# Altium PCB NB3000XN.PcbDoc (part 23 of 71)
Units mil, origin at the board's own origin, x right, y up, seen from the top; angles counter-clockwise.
Board outline 9527.56 x 6929.77 mil, 6 copper layers (Top Layer, GND+SHIELD, MidLayer1, MidLayer2, P2 - 3V3+5V0, Bottom Layer), stack 62.375 mil thick; 832 components, 1027 nets, 4655 pads, 4981 vias.
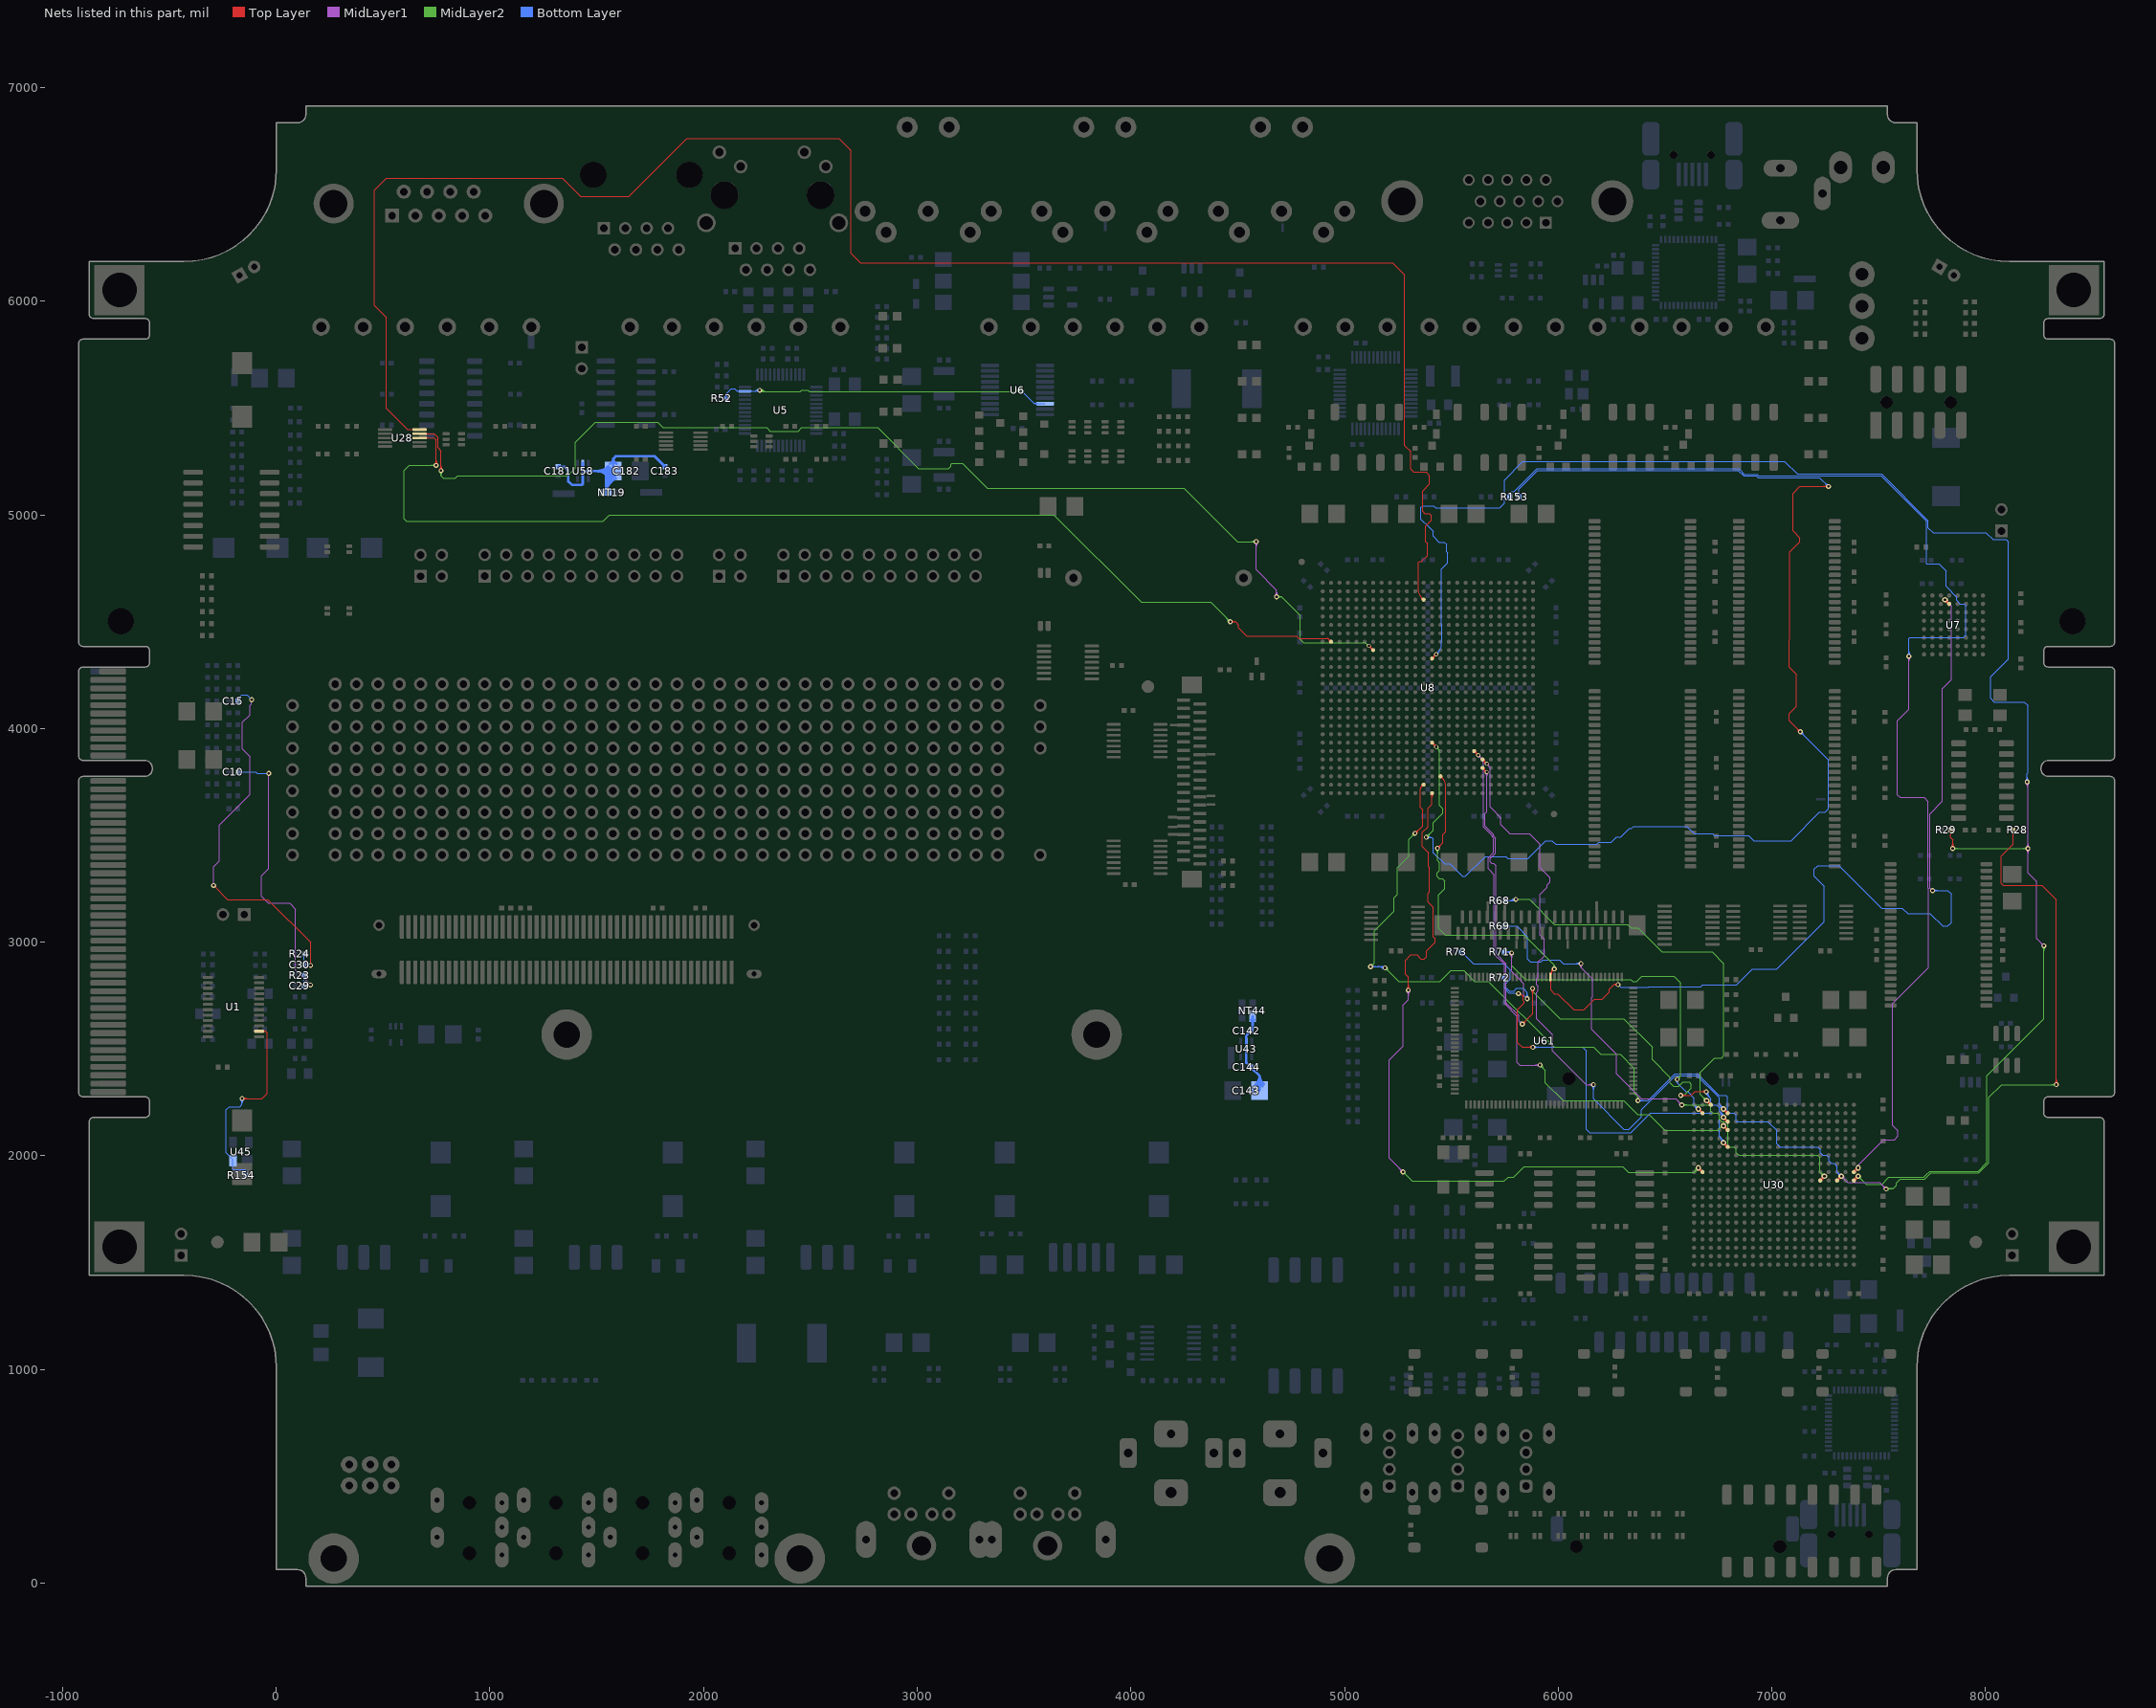
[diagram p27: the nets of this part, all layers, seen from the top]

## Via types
v1: diameter 23, hole 11.81, Top Layer to Bottom Layer, 3672 vias
v2: diameter 26, hole 11.81, Top Layer to Bottom Layer, 461 vias
v3: diameter 19, hole 11.81, Top Layer to Bottom Layer, tented both sides, 396 vias
v4: diameter 23.62, hole 11.81, Top Layer to Bottom Layer, 288 vias
v5: diameter 20, hole 11.81, Top Layer to Bottom Layer, 91 vias
v6: diameter 23, hole 11.81, Top Layer to Bottom Layer, tented both sides, 50 vias
v7: diameter 31, hole 11.81, Top Layer to Bottom Layer, 15 vias
v8: diameter 27.56, hole 11.81, Top Layer to Bottom Layer, tented both sides, 4 vias
v9: diameter 29, hole 11.81, Top Layer to Bottom Layer, 3 vias
v10: diameter 21, hole 11.81, Top Layer to Bottom Layer, 1 vias

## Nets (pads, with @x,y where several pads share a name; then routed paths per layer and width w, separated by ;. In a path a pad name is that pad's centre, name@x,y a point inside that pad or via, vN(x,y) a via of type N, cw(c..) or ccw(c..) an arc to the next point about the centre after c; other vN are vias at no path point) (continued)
CODEC_AUD.L: C10.2 C29.1 R23.1 | length 1510.1
  MidLayer1 w4: v1(-35,3790) -35.7,3790 -35.81,3789.89 -35.81,3344.19 -69.25,3310.75 -69.25,3214.25 -37.69,3182.69 62.31,3182.69 90.19,3154.81 90.19,2870.71 v1(160.86,2800.04)
  Bottom Layer w4: C10.2@-179.33,3795.91 -95,3795.91 -89.09,3790 v1(-35,3790) ; C29.1@130.67,2795 C29.1@131.18,2795.51 ; R23.1@130.67,2844.49 R23.1@131.18,2845 C29.1@131.18,2795.51 ; C29.1@132.1,2793.89 cw(c144.6,2784.27) 144.6,2800.04 ; C29.1@135.27,2791.45 cw(c152.73,2778.01) v1@152.73,2800.04 ; C29.1@137.61,2801.94 ccw(c142.19,2806.52) C29.1@142.19,2800.04 ; C29.1@138.44,2789.01 cw(c160.86,2771.75) v1(160.86,2800.04) 135.71,2800.04 C29.1@131.18,2795.51 ; v1@154.14,2793.32 ccw(c137.92,2777.11) 137.92,2800.04 ccw(c137.92,2822.98) v1@154.14,2806.76 ; v1@156.97,2796.15 ccw(c147.58,2786.76) 147.58,2800.04 ccw(c147.58,2813.32) v1@156.97,2803.93
CODEC_AUD.R: C15.2 C30.1 R24.1 | length 1882
  Top Layer w4: v1(-293.14,3265.71) -227.44,3200 -40,3200 160.86,2999.14 v1(160.86,2891.71)
  MidLayer1 w4: v1(-293.14,3265.71) -293.14,3353.62 -266.31,3380.45 -266.31,3548.69 -122.48,3692.52 -122.48,3869.56 -138.29,3885.37 ; -138.66,3885.37 -157.48,3904.19 -157.48,4029.34 -123,4063.82 -123,4107.81 -116.52,4114.29 v1@-116.52,4135
  Bottom Layer w4: C15.2@-179.33,4128.64 -179.33,4138.55 -160.94,4156.94 -136.94,4156.94 v1(-115,4135) ; R24.1@130.67,2944.49 R24.1@131.18,2945 131.18,2895.51 C30.1@130.67,2895 ; C30.1@140.11,2895 cw(c140.11,2871.62) v1@156.91,2887.88 ; 145.87,2895 ccw(c145.87,2906.69) v1@154.14,2898.43 ; 149.55,2895 cw(c149.55,2880.76) v1@159.78,2890.66 ; v1@154.03,2885.1 ccw(c130.67,2862.49) C30.1@130.67,2895 ; v1(160.86,2891.71) 157.56,2895 C30.1@130.67,2895
CODEC_RST: R154.1 U1.14 U45.2 | length 1071.8
  Top Layer w4: v1(-159.81,2268.37) -66.63,2268.37 -43.14,2291.86 -43.14,2575.03 -51.14,2583.03 U1.14@-79.84,2583.03 ; v1@-155.92,2264.49 cw(c-146.53,2255.1) -146.53,2268.37 cw(c-146.53,2281.65) v1@-155.92,2272.26 ; v1@-153.09,2261.66 cw(c-136.87,2245.44) -136.87,2268.37 cw(c-136.87,2291.31) v1@-153.09,2275.09 ; U1.14@-60.1,2579.43 cw(c-51.42,2570.75) -51.42,2583.03 cw(c-51.42,2595.31) U1.14@-60.1,2586.63
  Bottom Layer w4: v1@-166.53,2261.66 cw(c-182.74,2245.44) -159.81,2245.44 cw(c-136.87,2245.44) v1@-153.09,2261.66 ; v1@-163.7,2264.49 cw(c-173.09,2255.1) -159.81,2255.1 cw(c-146.53,2255.1) v1@-155.92,2264.49 ; v1(-159.81,2268.37) -159.81,2240 -169.81,2230 -220,2230 -235,2215 -235,2015 -202.85,1982.85 U45.2@-202.85,1976.69 -202.85,1937.85 -200,1935 -146.32,1935 -141.32,1930 R154.1@-141.32,1910
COMA: C142.1 C143.2 C144.1 NT44.2 U43.2 | length 667.1
  Bottom Layer w12: C144.1@4555.84,2415 ccw(c4541.81,2415) 4551.73,2424.92 ccw(c4561.65,2434.84) C144.1@4561.65,2420.81 ; C142.1@4555.84,2585 cw(c4541.81,2585) 4551.73,2575.08 cw(c4561.65,2565.16) C142.1@4561.65,2579.19 ; C142.1@4557.54,2589.11 ccw(c4528.04,2618.61) 4569.76,2618.61 ; C144.1@4561.65,2409.19 cw(c4561.65,2395.16) 4571.57,2405.08 cw(c4581.49,2415) C144.1@4567.46,2415 ; NT44.2@4562.87,2636.75 cw(c4546.23,2620.11) 4569.76,2620.11 cw(c4593.3,2620.11) NT44.2@4576.66,2636.75 ; NT44.2@4569.76,2653.9 4569.76,2593.11 C142.1@4561.65,2585 4540,2563.35 U43.2@4540,2537.4 4540,2436.65 C144.1@4561.65,2415 4602.99,2373.66 ; C143.2@4583.64,2336.12 ccw(c4556.91,2373.66) 4602.99,2373.66 ; C143.2@4590.6,2326.35 ccw(c4573.48,2350.38) 4602.99,2350.38 ccw(c4632.5,2350.38) C143.2@4615.39,2326.35 ; C143.2@4602.99,2305 4602.99,2373.66 ; C143.2@4622.35,2336.12 cw(c4649.07,2373.66) 4602.99,2373.66
COMB: C181.1 C182.2 C183.1 NT19.2 U58.2 | length 1566.9
  Bottom Layer w12: C181.1@1320,5225.67 1349.33,5225.67 1366.58,5208.42 1366.58,5158.42 1385,5140 1430,5140 1435,5145 1435,5205 ; C181.1@1324.11,5221.56 cw(c1334.03,5211.64) 1334.03,5225.67 cw(c1334.03,5239.7) C181.1@1324.11,5229.78 ; U58.2@1435,5242.4 1435,5205 ; NT19.2@1537,5112.13 ccw(c1520.36,5128.77) 1543.9,5128.77 ccw(c1567.43,5128.77) NT19.2@1550.79,5112.13 ; NT19.2@1543.9,5099.52 cw(c1620.99,5099.52) C182.2@1590.64,5170.39 ; NT19.2@1543.9,5105.24 1543.9,5171.4 C182.2@1577.5,5205 ; NT19.2@1543.9,5117.71 cw(c1613.2,5117.71) C182.2@1585.91,5181.42 ; 1543.9,5135.91 cw(c1605.41,5135.91) C182.2@1581.19,5192.45 ; 1543.9,5154.1 cw(c1597.61,5154.1) C182.2@1576.46,5203.48 ; C182.2@1543.9,5172.3 cw(c1589.82,5172.3) C182.2@1571.74,5214.51 ; C182.2@1553.9,5181.4 ccw(c1496.94,5124.44) 1496.94,5205 ccw(c1496.94,5285.56) C182.2@1553.9,5228.6 ; C182.2@1562.39,5189.89 ccw(c1525.91,5153.41) 1525.91,5205 ccw(c1525.91,5256.59) C182.2@1562.39,5220.11 ; C182.2@1562.79,5238.89 ccw(c1551.2,5262.5) 1577.5,5262.5 ccw(c1603.8,5262.5) C182.2@1592.21,5238.89 ; C183.1@1814.19,5225.67 ccw(c1800.16,5225.67) 1810.08,5235.59 ccw(c1820,5245.51) C183.1@1820,5231.48 ; C183.1@1820,5225.67 1770.67,5275 1590,5275 1577.5,5262.5 C182.2@1577.5,5205 1435,5205
CRS_U: R52.1 U5.23 U6.8 | length 1968.1
  MidLayer2 w4: v1(2262.86,5583.71) 2269.06,5577.5 2452.25,5577.5 2459.27,5584.52 2488.69,5584.52 2495.71,5577.5 3478.65,5577.5 v1(3484.86,5583.71) ; v1@2263.92,5584.77 ccw(c2281.47,5602.32) 2281.47,5577.5 ; v1@2266.75,5587.6 ccw(c2291.12,5611.97) 2291.12,5577.5 ; v1@2269.57,5590.43 ccw(c2300.78,5621.63) 2300.78,5577.5 ; 3446.94,5577.5 ccw(c3446.94,5621.63) v1@3478.14,5590.43 ; 3456.59,5577.5 ccw(c3456.59,5611.97) v1@3480.97,5587.6 ; 3466.25,5577.5 ccw(c3466.25,5602.32) v1@3483.8,5584.77
  Bottom Layer w4: R52.1@2100.04,5552.5 ccw(c2088.21,5566.03) 2106.18,5566.03 ; R52.1@2102.68,5549.49 ccw(c2095.92,5557.22) 2106.18,5557.22 ccw(c2116.44,5557.21) R52.1@2109.68,5549.49 ; R52.1@2106.18,5545 2106.18,5566.03 ; R52.1@2112.32,5552.5 cw(c2124.16,5566.03) 2106.18,5566.03 ; U5.23@2167.19,5575.75 ccw(c2160.36,5568.93) 2160.36,5578.58 ccw(c2160.36,5588.24) U5.23@2167.19,5581.41 ; U5.23@2219.9,5575.75 cw(c2226.73,5568.93) 2226.73,5578.58 cw(c2226.73,5588.24) U5.23@2219.9,5581.41 ; 2227.55,5578.58 ccw(c2227.55,5619.02) v1@2256.14,5590.43 ; 2237.21,5578.58 ccw(c2237.21,5609.36) v1@2258.97,5587.6 ; 2246.86,5578.58 ccw(c2246.86,5599.7) v1@2261.8,5584.77 ; 2252.29,5578.58 cw(c2252.29,5573.15) v1@2256.14,5576.99 ; v1(2262.86,5583.71) 2257.73,5578.58 U5.23@2193.54,5578.58 2156.86,5578.58 2145.4,5590.04 2130.19,5590.04 2106.18,5566.03 ; v1@3484.86,5574.21 cw(c3484.86,5551.27) 3501.07,5567.49 cw(c3517.29,5583.71) v1@3494.36,5583.71 ; v1@3484.86,5578.21 cw(c3484.86,5564.93) 3494.25,5574.32 cw(c3503.64,5583.71) v1@3490.36,5583.71 ; v1(3484.86,5583.71) 3547.54,5521.02 U6.8@3598.94,5521.02 ; U6.8@3560.62,5516.17 ccw(c3548.91,5504.47) 3548.91,5521.02 ccw(c3548.92,5537.58) U6.8@3560.62,5525.87
DAC.CLK: U8.C13 U28.10 | length 8540.9
  Top Layer w4: U28.10@640.42,5396.54 ccw(c633.59,5389.71) 633.59,5399.37 ccw(c633.59,5409.03) U28.10@640.42,5402.2 ; U28.10@670.71,5399.37 615,5399.37 515,5499.37 515,5925 460,5980 460,6520 515,6575 1340,6575 1425,6490 1650,6490 1922,6762 2633,6762 2690,6705 2690,6225 2735,6180 5225,6180 5281.86,6123.14 5281.86,5325.04 5309.86,5297.04 5309.86,5294 ; 5309.86,5250.04 5309.86,5294 ; U8.C13@5362.97,4603.39 ccw(c5345.25,4603.39) 5357.78,4615.92 ; U8.C13@5370.31,4610.73 cw(c5370.31,4628.45) 5357.78,4615.92 ; 5309.86,5294 5309.86,5214.14 5323.96,5200.04 5381.86,5200.04 5398.52,5183.37 5398.52,5145.71 5365.19,5112.37 5365.19,5016.71 5375.52,5006.37 5398.52,5006.37 5406.86,4998.04 5406.86,4975.04 5379.19,4947.37 5379.19,4875.04 5387.5,4866.73 5387.5,4810.06 5360.44,4783 5350,4783 5346.45,4779.45 5346.45,4773 5346.45,4724.74 5346.45,4720 5346.45,4710 5346.45,4643.27 ccw(c5385.13,4643.27) 5357.78,4615.92
DAC.CS: U8.J7 U28.9 | length 5946.3
  Top Layer w4: U28.9@670.71,5379.69 740.31,5379.69 756.86,5363.14 756.86,5314.71 771.52,5300.04 v1(771.52,5207.37) ; U28.9@701,5376.86 cw(c707.83,5370.03) 707.83,5379.69 cw(c707.83,5389.34) U28.9@701,5382.51 ; v1@764.81,5214.09 ccw(c748.59,5230.31) 771.52,5230.31 ccw(c794.46,5230.31) v1@778.24,5214.09 ; v1@767.64,5211.26 ccw(c758.25,5220.65) 771.52,5220.65 ccw(c784.8,5220.65) v1@775.41,5211.26 ; v3(5114.41,4386.85) U8.J7@5134.09,4367.17 ; U8.J7@5126.59,4367.17 ccw(c5108.49,4367.17) 5121.29,4379.97 ccw(c5134.09,4392.77) U8.J7@5134.09,4374.67 ; U8.J7@5126.75,4367.17 ccw(c5109.03,4367.17) 5121.56,4379.7 ccw(c5134.09,4392.23) U8.J7@5134.09,4374.51 ; 5127.21,4374.05 ccw(c5114.41,4361.24) 5114.41,4379.35 cw(c5114.41,4361.24) 5127.21,4374.05 ; 5127.21,4374.05 cw(c5140.02,4386.85) 5121.91,4386.85 ccw(c5140.02,4386.85) 5127.21,4374.05
  MidLayer1 w4: v1@4580.14,4868.32 cw(c4563.92,4852.11) 4586.86,4852.11 cw(c4609.79,4852.11) v1@4593.57,4868.32 ; v1@4582.97,4871.15 cw(c4573.58,4861.76) 4586.86,4861.76 cw(c4600.14,4861.76) v1@4590.75,4871.15 ; v1(4586.86,4875.04) 4586.86,4743.39 4681.86,4648.39 v1(4681.86,4616.71) ; v1@4675.14,4623.43 ccw(c4658.92,4639.64) 4681.86,4639.64 ccw(c4704.79,4639.64) v1@4688.57,4623.43 ; v1@4677.97,4620.6 ccw(c4668.58,4629.99) 4681.86,4629.99 ccw(c4695.14,4629.99) v1@4685.75,4620.6
  MidLayer2 w4: v1@764.81,5200.66 cw(c748.59,5184.44) 771.52,5184.44 cw(c794.46,5184.44) v1@778.24,5200.66 ; v1@767.64,5203.49 cw(c758.25,5194.1) 771.52,5194.1 cw(c784.8,5194.1) v1@775.41,5203.49 ; v1(771.52,5207.37) 771.52,5183.48 782.72,5172.28 837.28,5172.28 848.71,5183.71 1365.02,5183.71 1400,5218.69 1400,5340.2 1493.5,5433.71 1786.29,5433.71 1810,5410 2294.81,5410 2312.62,5392.19 2443.04,5392.19 2459.39,5408.54 2815.03,5408.54 3006.38,5217.19 3147.38,5217.19 3157.81,5227.62 3157.81,5235.84 3163.68,5241.71 3211.98,5241.71 3328.65,5125.04 4248.52,5125.04 4498.52,4875.04 v1(4586.86,4875.04) ; v1@4580.14,4868.32 ccw(c4563.92,4852.11) 4563.92,4875.04 ccw(c4563.92,4897.98) v1@4580.14,4881.76 ; v1@4582.97,4871.15 ccw(c4573.58,4861.76) 4573.58,4875.04 ccw(c4573.58,4888.32) v1@4582.97,4878.93 ; v1(4681.86,4616.71) 4705.19,4616.71 4770.79,4551.11 4792,4529.9 4792,4418 4807.64,4402.36 4860,4402.36 4870,4402.36 4997.36,4402.36 5090.9,4402.36 cw(c5090.9,4388.31) 5100.83,4398.24 ; v1@4685.75,4612.82 cw(c4695.14,4603.43) 4695.14,4616.71 cw(c4695.14,4629.99) v1@4685.75,4620.6 ; v1@4688.57,4609.99 cw(c4704.79,4593.77) 4704.79,4616.71 cw(c4704.79,4639.64) v1@4688.57,4623.43 ; v3@5106.94,4386.2 ccw(c5088.9,4384.62) 5100.54,4398.49 ccw(c5112.18,4412.36) v3@5113.76,4394.32
DAC.DIN: U8.H2 U28.8 | length 5482.2
  Top Layer w4: U28.8@698.18,5360 U28.8@676.2,5360 ; U28.8@701,5357.17 cw(c707.83,5350.34) 707.83,5360 cw(c707.83,5369.66) U28.8@701,5362.83 ; v1@741.81,5238.76 ccw(c725.59,5254.98) 748.52,5254.98 ccw(c771.46,5254.98) v1@755.24,5238.76 ; v1@744.64,5235.93 ccw(c735.25,5245.32) 748.52,5245.32 ccw(c761.8,5245.32) v1@752.41,5235.93 ; v1(748.52,5232.04) 748.52,5351.48 740,5360 U28.8@676.2,5360 ; v1(4465.19,4500.04) 4489.96,4500.04 4505,4485 4505,4471.31 4542.44,4433.87 4759,4433.87 4774.01,4433.87 4785.84,4422.04 4790.84,4422.04 4801,4422.04 4860,4422.04 4870,4422.04 4917.53,4422.04 cw(c4917.53,4411.89) 4924.71,4419.07 ; v1@4469.08,4496.15 cw(c4478.47,4486.76) 4478.47,4500.04 cw(c4478.47,4513.32) v1@4469.08,4503.93 ; v1@4471.91,4493.32 cw(c4488.13,4477.11) 4488.13,4500.04 cw(c4488.13,4522.98) v1@4471.91,4506.76 ; U8.H2@4929.9,4406.54 ccw(c4912.17,4406.54) 4924.71,4419.07 ; U8.H2@4937.24,4413.88 cw(c4937.24,4431.6) 4924.71,4419.07 ; U28.8@676.2,5360 U28.8@670.71,5360 U28.8@676.2,5360
  MidLayer2 w4: v1@741.81,5225.32 ccw(c725.59,5209.11) 725.59,5232.04 ccw(c725.59,5254.98) v1@741.81,5238.76 ; v1@744.64,5228.15 ccw(c735.25,5218.76) 735.25,5232.04 ccw(c735.25,5245.32) v1@744.64,5235.93 ; v1(748.52,5232.04) 622.04,5232.04 598.52,5208.52 598.52,4981.48 610,4970 1530,4970 1560.04,5000.04 1635,5000.04 3625,5000 ; 3620,5000 3625,5000 ; v1@4455.69,4500.04 ccw(c4432.76,4500.04) 4448.97,4516.26 ccw(c4465.19,4532.48) v1@4465.19,4509.54 ; v1@4459.69,4500.04 ccw(c4446.41,4500.04) 4455.8,4509.43 ccw(c4465.19,4518.82) v1@4465.19,4505.54 ; v1(4465.19,4500.04) 4373.52,4591.71 4048.52,4591.71 3640.23,5000 3625,5000
DB_CLK1: R153.1 U30.A9 | length 6069
  Top Layer w8: U30.A9@7384.02,1924.06 v2(7403.7,1943.74) ; U30.A9@7384.02,1929.9 ccw(c7384.02,1944) 7393.99,1934.03 ccw(c7403.96,1924.06) U30.A9@7389.86,1924.06 ; v2@7394.7,1943.74 cw(c7372.97,1943.74) 7388.34,1928.38 cw(c7403.7,1913.01) v2@7403.7,1934.74
  MidLayer1 w4: v2(7403.7,1943.74) 7403.7,1956.98 7405.46,1958.74 7407.22,1958.74 7523.52,2075.04 7573.52,2075.04 7590.19,2091.71 7590.19,2116.71 7565.19,2141.71 7565.19,2713.73 7732.52,2881.06 7732.52,3251.42 7731.86,3252.09 7731.86,3658.14 7712.35,3677.65 7600.23,3677.65 7588.29,3689.59 7588.29,4036.76 7641.52,4090 v1(7641.52,4338.37) ; v1@7634.81,4331.66 cw(c7618.59,4315.44) 7641.52,4315.44 cw(c7664.46,4315.44) v1@7648.24,4331.66 ; v1@7637.64,4334.49 cw(c7628.25,4325.1) 7641.52,4325.1 cw(c7654.8,4325.1) v1@7645.41,4334.49
  Bottom Layer w4: R153.1@5769.77,5093.89 ccw(c5766.66,5100.34) 5773.82,5100.34 ; R153.1@5773.82,5085 5773.82,5100.34 ; R153.1@5777.87,5093.89 cw(c5780.98,5100.34) 5773.82,5100.34 ; v1@7634.81,4345.09 ccw(c7618.59,4361.31) 7641.52,4361.31 ccw(c7664.46,4361.31) v1@7648.24,4345.09 ; v1@7637.64,4342.26 ccw(c7628.25,4351.65) 7641.52,4351.65 ccw(c7654.8,4351.65) v1@7645.41,4342.26 ; v1(7641.52,4338.37) 7641.52,4421.37 7645.52,4425.37 7896.52,4425.37 7908.52,4437.37 7908.52,4575.04 7900.19,4583.37 7881.86,4583.37 7865.19,4600.04 7865.19,4615.04 7815.19,4665.04 7815.19,4736.71 7781.86,4770.04 7725.19,4770.04 7723.52,4771.71 7723.52,4970.71 7510.86,5183.37 6938.43,5183.37 6931.09,5190.71 6871.8,5190.71 6845.8,5216.71 5965,5216.71 5901.71,5216.71 5793.37,5108.37 5781.86,5108.37 5773.82,5100.34
DB_CLOCKS.FPGA_CLK: R28.1 U8.AE13 U30.C10 | length 7750.4
  Top Layer w4: v1(5330,3510) v1@5330.1,3509.9 ; v1@5330,3515.5 ccw(c5330,3529.27) 5339.73,3519.53 ; v1@5330,3519.5 ccw(c5330,3542.92) 5346.56,3526.36 ; v1@5333.05,3509.9 v1@5330.1,3509.9 ; v1@5335.5,3510 cw(c5348.29,3510) 5339.25,3519.04 ; v1@5339.5,3510 cw(c5361.95,3510) 5346.07,3525.87 ; U8.AE13@5362.97,3737.24 cw(c5345.25,3737.24) 5357.78,3724.71 ; U8.AE13@5370.31,3729.9 ccw(c5370.31,3712.17) 5357.78,3724.71 ; R28.1@8122.23,3517.92 cw(c8106.32,3502.01) 8128.82,3502.01 cw(c8151.32,3502.01) R28.1@8135.41,3517.92 ; R28.1@8125.06,3520.75 cw(c8115.98,3511.67) 8128.82,3511.67 cw(c8141.66,3511.67) R28.1@8132.58,3520.75 ; R28.1@8128.82,3525 8128.82,3458.37 8073.52,3403.08 8073.52,3275.04 8081.56,3267 8263,3267 8331.86,3198.14 v1(8331.86,2333.37) ; v1@8325.14,2340.09 ccw(c8308.92,2356.31) 8331.86,2356.31 ccw(c8354.79,2356.31) v1@8338.57,2340.09 ; v1@8327.97,2337.26 ccw(c8318.58,2346.65) 8331.86,2346.65 ccw(c8345.14,2346.65) v1@8335.75,2337.26 ; v1@5330.1,3509.9 5365.19,3544.99 5365.19,3619.81 5354.81,3630.19 5354.81,3660 5354.81,3670 5354.81,3717.53 cw(c5364.96,3717.53) 5357.78,3724.71
  Top Layer w8: U30.C10@7305.28,1884.68 v2(7324.96,1904.37) ; U30.C10@7305.28,1890.53 ccw(c7305.28,1904.63) 7315.25,1894.66 ccw(c7325.22,1884.68) U30.C10@7311.12,1884.68 ; v2@7315.96,1904.37 cw(c7294.23,1904.37) 7309.6,1889.01 cw(c7324.96,1873.64) v2@7324.96,1895.37
  MidLayer1 w4: v2@7324.96,1893.37 cw(c7324.96,1866.81) 7343.74,1885.59 cw(c7362.52,1904.37) v2@7335.96,1904.37 ; v2@7324.96,1897.37 cw(c7324.96,1880.47) 7336.91,1892.42 cw(c7348.86,1904.37) v2@7331.96,1904.37 ; v2(7324.96,1904.37) 7354.29,1875.04 7504.96,1875.04 v1(7535,1845) v1@7536.9,1845 ; v1@7525.5,1845 ccw(c7502.56,1845) 7518.78,1861.22 ccw(c7535,1877.43) v1@7535,1854.5 ; v1@7529.5,1845 ccw(c7516.22,1845) 7525.61,1854.39 ccw(c7535,1863.78) v1@7535,1850.5
  MidLayer2 w4: v4(5121.9,2885) 5140.52,2903.63 5140.52,3053.36 5231.86,3144.69 5231.86,3208.06 5247.86,3224.06 5247.86,3350.02 5301.19,3403.35 5301.19,3481.19 v1(5330,3510) v1@5325.82,3510 ; v4@5121.9,2890.81 ccw(c5121.9,2904.84) 5131.82,2894.92 ccw(c5141.74,2885) v4@5127.71,2885 ; v4@5121.9,2894.81 ccw(c5121.9,2918.5) 5138.65,2901.75 ccw(c5155.39,2885) v4@5131.71,2885 ; v4@5190,2870.19 cw(c5190,2846.5) 5206.75,2863.25 cw(c5223.5,2880) v4@5199.81,2880 ; v4@5190,2874.19 cw(c5190,2860.16) 5199.92,2870.08 cw(c5209.84,2880) v4@5195.81,2880 ; v4(5190,2880) 5254.13,2815.87 5446.44,2815.87 5497.2,2866.63 5557.97,2866.63 5607.9,2816.71 5673.52,2816.71 5981.86,2508.37 6165.19,2508.37 6198.52,2475.04 6290.19,2475.04 6356.86,2408.37 6356.86,2291.71 6373.52,2275.04 ; v1@5320.5,3510 cw(c5297.56,3510) 5313.78,3493.78 cw(c5330,3477.56) v1@5330,3500.5 ; v1@5324.5,3510 cw(c5311.22,3510) 5320.61,3500.61 cw(c5330,3491.22) v1@5330,3504.5 ; v1@6368.68,2266.55 ccw(c6363.66,2275.04) 6373.52,2275.04 ; v1(6373.52,2258.37) 6373.52,2275.04 ; v1@6378.36,2266.55 cw(c6383.39,2275.04) 6373.52,2275.04 ; v1(7535,1845) 7537.19,1847.19 7567.38,1847.19 7582.5,1862.31 7582.5,1872.25 7601.75,1891.5 7714.94,1891.5 7743.44,1920 ; v1@7538.89,1841.11 cw(c7553.56,1826.44) 7553.56,1847.19 ; v1@7541.72,1838.28 cw(c7563.22,1816.78) 7563.22,1847.19 ; v1@7541.72,1851.72 ccw(c7552.65,1862.65) 7552.65,1847.19 ; 7734.85,1911.41 7743.44,1920 ; v1@8325.14,2326.66 ccw(c8308.92,2310.44) 8308.92,2333.37 ccw(c8308.92,2356.31) v1@8325.14,2340.09 ; v1@8327.97,2329.49 ccw(c8318.58,2320.1) 8318.58,2333.37 ccw(c8318.58,2346.65) v1@8327.97,2337.26 ; v1(8331.86,2333.37) 8075.19,2333.37 8015.19,2273.37 8015.19,1966.71 7973.52,1925.04 7968.48,1920 7743.44,1920
  Bottom Layer w4: v4(5121.9,2885) 5185,2885 v4(5190,2880) ; v4@5126.01,2880.89 cw(c5135.93,2870.97) 5135.93,2885 cw(c5135.93,2899.03) v4@5126.01,2889.11 ; v4@5128.84,2878.06 cw(c5145.58,2861.31) 5145.58,2885 cw(c5145.58,2908.69) v4@5128.84,2891.94 ; 5154.24,2885 cw(c5154.24,2844.24) v4@5183.06,2873.06 ; 5163.9,2885 cw(c5163.9,2853.9) v4@5185.89,2875.89 ; 5173.56,2885 cw(c5173.56,2863.56) v4@5188.72,2878.72 ; 5178.39,2885 ccw(c5178.39,2891.61) v4@5183.06,2886.94 ; v1(6373.52,2258.37) 6410,2258.37 6415.19,2258.37 6420.54,2258.37 6546.21,2384.04 6605,2384.04 6651.8,2384.04 6752.46,2283.37 6785.19,2283.37 6793.52,2275.04 6793.52,2208.37 6801.86,2200.04 6823.86,2200.04 6832.19,2191.71 6832.19,2163.37 6835.19,2160.37 6981.86,2160.37 7023.52,2118.71 7023.52,2056.04 7037.86,2041.71 7214.49,2041.71 7227.22,2028.98 7227.22,2014.61 7238.35,2003.48 7256.52,2003.48 7266.59,1993.41 7266.59,1975.24 7277.72,1964.11 7292.09,1964.11 7305.96,1950.24 7305.96,1923.37 v2(7324.96,1904.37) v2@7323.52,1904.37 ; v1@6377.41,2254.49 cw(c6386.8,2245.1) 6386.8,2258.37 cw(c6386.8,2271.65) v1@6377.41,2262.26 ; v1@6380.24,2251.66 cw(c6396.46,2235.44) 6396.46,2258.37 cw(c6396.46,2281.31) v1@6380.24,2265.09 ; v2@7313.96,1904.37 ccw(c7287.4,1904.37) 7306.18,1923.15 ccw(c7324.96,1941.93) v2@7324.96,1915.37 ; v2@7317.96,1904.37 ccw(c7301.06,1904.37) 7313.01,1916.32 ccw(c7324.96,1928.27) v2@7324.96,1911.37
DB_CLOCKS.FPGA_CLK1: R153.2 U8.Y14 | length 6566.3
  Top Layer w4: U8.Y14@5409.69,3926.59 cw(c5409.69,3908.49) 5422.49,3921.29 cw(c5435.29,3934.09) U8.Y14@5417.19,3934.09 ; U8.Y14@5409.69,3926.75 cw(c5409.69,3909.03) 5422.22,3921.56 cw(c5434.75,3934.09) U8.Y14@5417.03,3934.09 ; U8.Y14@5409.69,3934.09 v3(5429.37,3914.41) ; v1@7124.02,3985.04 ccw(c7101.09,3985.04) 7117.31,4001.26 ccw(c7133.52,4017.48) v1@7133.52,3994.54 ; v1@7128.02,3985.04 ccw(c7114.75,3985.04) 7124.14,3994.43 ccw(c7133.52,4003.82) v1@7133.52,3990.54 ; v1(7133.52,3985.04) 7081.86,4036.71 7081.86,4070.04 7115.19,4103.37 7115.19,4253.39 7081.86,4286.73 7081.86,4413.71 7084.86,4416.71 7084.86,4827.04 7131.86,4874.04 7131.86,4891.71 7098.52,4925.04 7098.52,5100.04 7131.86,5133.37 v1(7265.19,5133.37) ; v1@7258.47,5126.66 ccw(c7242.26,5110.44) 7242.26,5133.37 ccw(c7242.26,5156.31) v1@7258.47,5140.09 ; v1@7261.3,5129.49 ccw(c7251.91,5120.1) 7251.91,5133.37 ccw(c7251.91,5146.65) v1@7261.3,5137.26 ; 5416.57,3927.21 cw(c5403.76,3914.41) 5421.87,3914.41 ccw(c5403.76,3914.41) 5416.57,3927.21 ; 5416.57,3927.21 ccw(c5429.37,3940.02) 5429.37,3921.91 cw(c5429.37,3940.02) 5416.57,3927.21
  MidLayer2 w4: v1(5382.2,3491.11) 5415,3523.91 5415,3560 5460,3605 5460,3625 5444.88,3640.12 5444.88,3660 5444.88,3670 5444.88,3797.36 5444.88,3890.9 ccw(c5430.83,3890.9) 5440.76,3900.83 ; v1@5382.2,3496.61 ccw(c5382.2,3509.89) 5391.59,3500.5 ccw(c5400.98,3491.11) v1@5387.7,3491.11 ; v1@5382.2,3500.61 ccw(c5382.2,3523.55) 5398.42,3507.33 ccw(c5414.64,3491.11) v1@5391.7,3491.11 ; v3@5428.72,3906.94 cw(c5427.14,3888.9) 5441.01,3900.54 cw(c5454.88,3912.18) v3@5436.84,3913.76
  Bottom Layer w4: v1(5382.2,3491.11) 5408.89,3491.11 5415.86,3484.14 5415.86,3419.02 5468.5,3366.37 5493.63,3366.37 5551.63,3308.37 5566.19,3308.37 5651.78,3393.96 5658.9,3401.08 5755.82,3401.08 5765.19,3391.71 5857.98,3391.71 5941.31,3475.04 5970.86,3475.04 5987.86,3458.04 6181.86,3458.04 6190.52,3466.71 6248.52,3466.71 6273.52,3491.71 6294.17,3491.71 6334.17,3531.71 6343.31,3531.71 6353.98,3542.37 6603.21,3542.37 6637.21,3508.37 6722.54,3508.37 6730.88,3500.04 6890.19,3500.04 6915.19,3475.04 7090.19,3475.04 7223.52,3608.37 7248.52,3608.37 7265.19,3625.04 7265.19,3853.37 v1(7133.52,3985.04) ; v1@5386.09,3487.22 cw(c5395.48,3477.83) 5395.48,3491.11 cw(c5395.48,3504.39) v1@5386.09,3495 ; v1@5388.92,3484.39 cw(c5405.14,3468.18) 5405.14,3491.11 cw(c5405.14,3514.05) v1@5388.92,3497.83 ; R153.2@5809.59,5092.08 ccw(c5793.68,5107.99) 5816.18,5107.99 ccw(c5838.68,5107.99) R153.2@5822.77,5092.08 ; R153.2@5812.42,5089.25 ccw(c5803.34,5098.33) 5816.18,5098.33 ccw(c5829.02,5098.33) R153.2@5819.94,5089.25 ; R153.2@5816.18,5085 5816.18,5119.87 5904.69,5208.37 6842.82,5208.37 6868.48,5182.71 6927.78,5182.71 6935.45,5175.04 7223.52,5175.04 v1(7265.19,5133.37) ; v1@7133.52,3975.54 cw(c7133.52,3952.61) 7149.74,3968.82 cw(c7165.96,3985.04) v1@7143.02,3985.04 ; v1@7133.52,3979.54 cw(c7133.52,3966.26) 7142.91,3975.65 cw(c7152.3,3985.04) v1@7139.02,3985.04 ; v1@7255.69,5133.37 ccw(c7232.76,5133.37) 7248.97,5149.59 ccw(c7265.19,5165.81) v1@7265.19,5142.87 ; v1@7259.69,5133.37 ccw(c7246.41,5133.37) 7255.8,5142.76 ccw(c7265.19,5152.15) v1@7265.19,5138.87
DB_CLOCKS.REF_CLK: R29.1 U8.K14 U30.A10 | length 9087.7
  Top Layer w4: U8.K14@5409.69,4327.8 v3(5429.37,4347.48) ; U8.K14@5409.69,4335.14 ccw(c5409.69,4352.86) 5422.22,4340.33 ccw(c5434.75,4327.8) U8.K14@5417.03,4327.8 ; U8.K14@5409.69,4335.3 ccw(c5409.69,4353.4) 5422.49,4340.6 ccw(c5435.29,4327.8) U8.K14@5417.19,4327.8 ; R29.1@7829.59,3517.92 cw(c7813.68,3502.01) 7836.18,3502.01 cw(c7858.68,3502.01) R29.1@7842.77,3517.92 ; R29.1@7832.42,3520.75 cw(c7823.34,3511.67) 7836.18,3511.67 cw(c7849.02,3511.67) R29.1@7839.94,3520.75 ; R29.1@7836.18,3525 7836.18,3490 7846.52,3479.66 v1(7846.52,3438.37) ; v1@7839.81,3445.09 ccw(c7823.59,3461.31) 7846.52,3461.31 ccw(c7869.46,3461.31) v1@7853.24,3445.09 ; v1@7842.64,3442.26 ccw(c7833.25,3451.65) 7846.52,3451.65 ccw(c7859.8,3451.65) v1@7850.41,3442.26 ; 5416.57,4334.68 cw(c5429.37,4321.87) 5429.37,4339.98 ccw(c5429.37,4321.87) 5416.57,4334.68 ; 5416.57,4334.68 ccw(c5403.76,4347.48) 5421.87,4347.48 cw(c5403.76,4347.48) 5416.57,4334.68
  Top Layer w8: U30.A10@7384.02,1884.68 v2(7403.7,1904.37) ; U30.A10@7384.02,1890.53 ccw(c7384.02,1904.63) 7393.99,1894.66 ccw(c7403.96,1884.68) U30.A10@7389.86,1884.68 ; v2@7394.7,1904.37 cw(c7372.97,1904.37) 7388.34,1889.01 cw(c7403.7,1873.64) v2@7403.7,1895.37
  MidLayer1 w4: v1@8188.28,3743.28 cw(c8163.56,3718.56) 8198.52,3718.56 ; v1@8191.11,3746.11 cw(c8173.21,3728.21) 8198.52,3728.21 ; v1@8191.81,3431.66 cw(c8175.59,3415.44) 8198.52,3415.44 cw(c8221.46,3415.44) v1@8205.24,3431.66 ; v1@8191.81,3445.09 ccw(c8175.59,3461.31) 8198.52,3461.31 ccw(c8221.46,3461.31) v1@8205.24,3445.09 ; v1@8193.94,3748.94 cw(c8182.87,3737.87) 8198.52,3737.87 ; v1@8194.64,3434.49 cw(c8185.25,3425.1) 8198.52,3425.1 cw(c8211.8,3425.1) v1@8202.41,3434.49 ; v1@8194.64,3442.26 ccw(c8185.25,3451.65) 8198.52,3451.65 ccw(c8211.8,3451.65) v1@8202.41,3442.26 ; v1(8195,3750) 8196.9,3750 8198.52,3748.37 v1(8198.52,3438.37) 8198.52,3325.04 8240.19,3283.37 8240.19,3016.71 v1(8273.52,2983.37) ; 8198.52,3735.57 cw(c8209.43,3735.57) v1@8201.72,3743.28 ; v1@8264.02,2983.37 ccw(c8241.09,2983.37) 8257.31,2999.59 ccw(c8273.52,3015.81) v1@8273.52,2992.87 ; v1@8268.02,2983.37 ccw(c8254.75,2983.37) 8264.13,2992.76 ccw(c8273.52,3002.15) v1@8273.52,2988.87
  MidLayer2 w4: v2@7403.7,1893.37 cw(c7403.7,1866.81) 7422.48,1885.59 cw(c7441.26,1904.37) v2@7414.7,1904.37 ; v2@7403.7,1897.37 cw(c7403.7,1880.47) 7415.65,1892.42 cw(c7427.6,1904.37) v2@7410.7,1904.37 ; v2(7403.7,1904.37) 7441.36,1866.71 7515.19,1866.71 7547.98,1899.5 7711.63,1899.5 7724.81,1912.68 7740.13,1928 7965.17,1928 8007.19,1970.02 8007.19,2375.37 8273.52,2641.71 v1(8273.52,2983.37) ; v1(7846.52,3438.37) v1(8198.52,3438.37) ; v1@7850.41,3434.49 cw(c7859.8,3425.1) 7859.8,3438.37 cw(c7859.8,3451.65) v1@7850.41,3442.26 ; v1@7853.24,3431.66 cw(c7869.46,3415.44) 7869.46,3438.37 cw(c7869.46,3461.31) v1@7853.24,3445.09 ; v1@8191.81,3431.66 ccw(c8175.59,3415.44) 8175.59,3438.37 ccw(c8175.59,3461.31) v1@8191.81,3445.09 ; v1@8194.64,3434.49 ccw(c8185.25,3425.1) 8185.25,3438.37 ccw(c8185.25,3451.65) v1@8194.64,3442.26 ; v1@8266.81,2976.66 cw(c8250.59,2960.44) 8273.52,2960.44 cw(c8296.46,2960.44) v1@8280.24,2976.66 ; v1@8269.64,2979.49 cw(c8260.25,2970.1) 8273.52,2970.1 cw(c8286.8,2970.1) v1@8277.41,2979.49
  Bottom Layer w4: v3@5428.72,4354.95 ccw(c5427.14,4372.99) 5441.01,4361.35 ; v3@5436.84,4348.13 cw(c5454.88,4349.71) 5441.01,4361.35 ; v1@8188.28,3756.72 ccw(c8172.06,3772.93) 8195,3772.93 ccw(c8217.94,3772.93) v1@8201.72,3756.72 ; v1@8191.11,3753.89 ccw(c8181.72,3763.28) 8195,3763.28 ccw(c8208.28,3763.28) v1@8198.89,3753.89 ; v1@8196.9,3750 v1(8195,3750) 8195,3790 8198.52,3793.52 8198.52,4108.37 8181.86,4125.04 8040.19,4125.04 8023.52,4141.71 8023.52,4241.71 8106.86,4325.04 8106.86,4873.14 8095,4885 8035,4885 8002.62,4917.38 7754.48,4917.38 7731.86,4940 7731.86,4973.69 7514.17,5191.37 7118.63,5191.37 7059.96,5250.04 5835.04,5250.04 5748.52,5163.52 5748.52,5055 5727.23,5033.71 5426.69,5033.71 5417.35,5043.04 5365.19,5043.04 5356.86,5034.71 5356.86,4980.37 5394.34,4942.89 5414.69,4922.54 5414.69,4900.31 5442.19,4872.81 5467.38,4872.81 5477.81,4862.38 5477.81,4826.94 5482.5,4822.25 5482.5,4774.64 5453.23,4745.37 5453.23,4724.74 5453.23,4720 5453.23,4710 5453.23,4503.9 5453.23,4484.48 5453.23,4410.36 5453.23,4390.86 cw(c5411.5,4390.86) 5441.01,4361.35
DB_JTAG.HARD.TCK: R69.1 U30.E10 | length 2800.1
  Top Layer w8: U30.E10@7226.54,1884.68 v2(7246.22,1904.37) ; U30.E10@7226.54,1890.53 ccw(c7226.54,1904.63) 7236.51,1894.66 ccw(c7246.48,1884.68) U30.E10@7232.38,1884.68 ; v2@7237.22,1904.37 cw(c7215.49,1904.37) 7230.86,1889.01 cw(c7246.22,1873.64) v2@7246.22,1895.37
  MidLayer1 w4: v1@6100.95,2892.6 cw(c6091.26,2880.38) 6106.86,2880.38 ; v1(6106.86,2900.04) 6106.86,2880.38 ; v1@6112.76,2892.6 ccw(c6122.46,2880.38) 6106.86,2880.38 ; v1@6569.02,2238.37 ccw(c6546.09,2238.37) 6562.31,2254.59 ccw(c6578.52,2270.81) v1@6578.52,2247.87 ; v1@6573.02,2238.37 ccw(c6559.75,2238.37) 6569.13,2247.76 ccw(c6578.52,2257.15) v1@6578.52,2243.87 ; v1(6578.52,2238.37) 6550.19,2266.71 6390.19,2266.71 6273.52,2383.37 6273.52,2475.04 6156.86,2591.71 6156.86,2741.71 6160.52,2745.37 6160.52,2826.71 6106.86,2880.38
  MidLayer2 w4: v1(6578.52,2238.37) 6712.19,2238.37 6715.19,2235.37 6715.19,2208.37 6723.52,2200.04 6745.19,2200.04 6753.52,2191.71 6753.52,2171.37 6765.19,2159.71 6784.19,2159.71 6793.86,2150.04 6793.86,2050.04 6802.19,2041.71 6824.52,2041.71 6832.86,2033.37 6832.86,2015.27 6846.02,2002.11 7214.72,2002.11 7225.85,1990.98 7225.85,1924.74 v2(7246.22,1904.37) ; v1@6582.41,2234.49 cw(c6591.8,2225.1) 6591.8,2238.37 cw(c6591.8,2251.65) v1@6582.41,2242.26 ; v1@6585.24,2231.66 cw(c6601.46,2215.44) 6601.46,2238.37 cw(c6601.46,2261.31) v1@6585.24,2245.09 ; v2@7235.22,1904.37 ccw(c7208.66,1904.37) 7227.44,1923.15 ccw(c7246.22,1941.93) v2@7246.22,1915.37 ; v2@7239.22,1904.37 ccw(c7222.32,1904.37) 7234.27,1916.32 ccw(c7246.22,1928.27) v2@7246.22,1911.37
  Bottom Layer w4: R69.1@5748.18,3075 5806.29,3075 5857,3024.29 5857,2921.71 5870,2908.71 5920,2908.71 5928,2916.71 6006.86,2916.71 6023.52,2900.04 v1(6106.86,2900.04) ; R69.1@5751.94,3071.24 cw(c5761.02,3062.16) 5761.02,3075 cw(c5761.02,3087.84) R69.1@5751.94,3078.76 ; R69.1@5754.77,3068.41 cw(c5770.68,3052.5) 5770.68,3075 cw(c5770.68,3097.5) R69.1@5754.77,3081.59 ; v1@6100.14,2893.32 ccw(c6083.92,2877.11) 6083.92,2900.04 ccw(c6083.92,2922.98) v1@6100.14,2906.76 ; v1@6102.97,2896.15 ccw(c6093.58,2886.76) 6093.58,2900.04 ccw(c6093.58,2913.32) v1@6102.97,2903.93
DB_JTAG.HARD.TDI: R72.1 U30.T6 | length 2280.4
  Top Layer w4: v1(5813.86,2759.51) 5815.98,2759.51 5817.28,2760.81 5817.28,2762.72 5815,2765 5815,2766.9 5837.19,2744.71 5837.19,2727.62 5840.19,2724.62 5840.19,2715.04 5810,2684.85 5810,2530 5831.63,2508.37 v1(5881.86,2508.37) ; v1@5814,2758.02 cw(c5815.82,2738.85) 5829.43,2752.47 ; v1@5814.38,2754.04 cw(c5816.86,2727.88) 5835.44,2746.46 ; v1@5875.14,2501.66 ccw(c5858.92,2485.44) 5858.92,2508.37 ccw(c5858.92,2531.31) v1@5875.14,2515.09 ; v1@5877.97,2504.49 ccw(c5868.58,2495.1) 5868.58,2508.37 ccw(c5868.58,2521.65) v1@5877.97,2512.26
  Top Layer w8: v2@6773.78,2052.85 cw(c6773.78,2031.12) 6789.14,2046.49 cw(c6804.51,2061.85) v2@6782.78,2061.85 ; v2(6773.78,2061.85) U30.T6@6793.46,2042.17 ; U30.T6@6787.62,2042.17 ccw(c6773.52,2042.17) 6783.49,2052.14 ccw(c6793.46,2062.11) U30.T6@6793.46,2048.01
  Bottom Layer w4: R72.1@5741.59,2827.92 cw(c5725.68,2812.01) 5748.18,2812.01 cw(c5770.68,2812.01) R72.1@5754.77,2827.92 ; R72.1@5744.42,2830.75 cw(c5735.34,2821.67) 5748.18,2821.67 cw(c5761.02,2821.67) R72.1@5751.94,2830.75 ; R72.1@5748.18,2835 5748.18,2783.93 5768.81,2763.3 5796.18,2763.3 5799.97,2759.51 v1(5813.86,2759.51) v1@5815.98,2759.51 ; v1(5881.86,2508.37) 6115.19,2508.37 6131.86,2491.71 6131.86,2125.04 6148.52,2108.37 6340.19,2108.37 6431.86,2200.04 6745.86,2200.04 6754.19,2191.71 6754.19,2091.71 6770.86,2075.04 6773.78,2075.04 v2(6773.78,2061.85) ; v1@5885.75,2504.49 cw(c5895.14,2495.1) 5895.14,2508.37 cw(c5895.14,2521.65) v1@5885.75,2512.26 ; v1@5888.57,2501.66 cw(c5904.79,2485.44) 5904.79,2508.37 cw(c5904.79,2531.31) v1@5888.57,2515.09 ; 6755.6,2090.3 cw(c6728.55,2063.25) v2@6766.78,2062.07 ; 6762.14,2083.76 cw(c6741.24,2062.86) v2@6770.78,2061.94 ; 6768.68,2077.22 cw(c6753.92,2062.47) v2@6774.78,2061.82
DB_JTAG.HARD.TDO: R71.1 R73.1 U30.W2 | length 2916.6
  Top Layer w8: v2@6655.67,2210.33 cw(c6655.67,2188.6) 6671.03,2203.97 cw(c6686.4,2219.33) v2@6664.67,2219.33 ; v2(6655.67,2219.33) U30.W2@6675.35,2199.65 ; U30.W2@6669.51,2199.65 ccw(c6655.41,2199.65) 6665.38,2209.62 ccw(c6675.35,2219.59) U30.W2@6675.35,2205.49
  MidLayer1 w4: v1@5775.14,2943.32 cw(c5758.92,2927.11) 5781.86,2927.11 cw(c5804.79,2927.11) v1@5788.57,2943.32 ; v1@5777.97,2946.15 cw(c5768.58,2936.76) 5781.86,2936.76 cw(c5795.14,2936.76) v1@5785.75,2946.15 ; v1(5781.86,2950.04) 5781.86,2863.14 5810.79,2834.21 5839.36,2805.64 5839.36,2750.64 v4(5855,2735)
  MidLayer2 w4: v1@5775.14,2943.32 cw(c5758.92,2927.11) 5781.86,2927.11 cw(c5804.79,2927.11) v1@5788.57,2943.32 ; v1@5777.97,2946.15 cw(c5768.58,2936.76) 5781.86,2936.76 cw(c5795.14,2936.76) v1@5785.75,2946.15 ; v1(5781.86,2950.04) 5781.86,2890.71 5847.19,2825.37 6339.86,2825.37 6348.52,2816.71 6366.52,2816.71 6391.52,2841.71 6541.19,2841.71 6573.52,2809.37 6573.52,2375.04 v1(6556.86,2358.37) ; v1@6556.86,2363.87 ccw(c6556.86,2377.15) 6566.25,2367.76 ccw(c6575.64,2358.37) v1@6562.36,2358.37 ; v1@6556.86,2367.87 ccw(c6556.86,2390.81) 6573.08,2374.59 ccw(c6589.29,2358.37) v1@6566.36,2358.37
  Bottom Layer w4: R73.1@5547.24,2945.19 cw(c5547.24,2918) 5566.46,2937.23 ; R73.1@5547.24,2949.19 cw(c5547.24,2931.66) 5559.63,2944.05 ; R73.1@5547.24,2952.76 R73.1@5547.24,2955 ; R73.1@5548.07,2955.62 5603.65,2900.04 5747.92,2900.04 5777,2870.96 5777,2828.12 5756.86,2807.98 5756.86,2786.57 5772.13,2771.3 5793.25,2771.3 5805.98,2784.02 5836.56,2784.02 5855,2765.59 v4(5855,2735) ; R73.1@5556.56,2954.51 ccw(c5574.37,2954.51) 5561.77,2941.91 ; R71.1@5751.94,2951.24 cw(c5761.02,2942.16) 5761.02,2955 cw(c5761.02,2967.84) R71.1@5751.94,2958.76 ; R71.1@5754.77,2948.41 cw(c5770.68,2932.5) 5770.68,2955 cw(c5770.68,2977.5) R71.1@5754.77,2961.59 ; R71.1@5757.5,2955 cw(c5757.5,2926.91) v1@5777.87,2946.25 ; 5766.81,2955 cw(c5766.81,2935.75) v1@5780.77,2949.01 ; 5770.89,2955 ccw(c5770.89,2961) v1@5775.14,2956.76 ; v1@5774.97,2943.5 ccw(c5748.18,2918.06) R71.1@5748.18,2955 5770.9,2955 5775.86,2950.04 v1(5781.86,2950.04) ; v4@5848.06,2741.94 ccw(c5831.31,2758.69) 5855,2758.69 ccw(c5878.69,2758.69) v4@5861.94,2741.94 ; v4@5850.89,2739.11 ccw(c5840.97,2749.03) 5855,2749.03 ccw(c5869.03,2749.03) v4@5859.11,2739.11 ; v1@6552.02,2350.2 cw(c6546.99,2341.71) 6556.86,2341.71 ; v1(6556.86,2358.37) 6556.86,2341.71 ; v1@6561.7,2350.2 ccw(c6566.73,2341.71) 6556.86,2341.71 ; v2@6644.67,2219.33 ccw(c6618.11,2219.33) 6636.89,2238.11 ccw(c6655.67,2256.89) v2@6655.67,2230.33 ; v2@6648.67,2219.33 ccw(c6631.77,2219.33) 6643.72,2231.28 ccw(c6655.67,2243.23) v2@6655.67,2226.33 ; v2(6655.67,2219.33) 6636.52,2238.48 6636.52,2270.37 6606.86,2300.04 6598.52,2300.04 6556.86,2341.71
DB_JTAG.HARD.TMS: R68.1 U30.V1 | length 2156.6
  Top Layer w8: v2@6695.04,2249.7 cw(c6695.04,2227.97) 6710.4,2243.34 cw(c6725.77,2258.7) v2@6704.04,2258.7 ; v2(6695.04,2258.7) U30.V1@6714.72,2239.02 ; U30.V1@6708.88,2239.02 ccw(c6694.78,2239.02) 6704.75,2248.99 ccw(c6714.72,2258.96) U30.V1@6714.72,2244.86
  MidLayer2 w4: v1(5802.19,3200.71) 5865.19,3200.71 5982.52,3083.37 6325.19,3083.37 6341.86,3066.71 6373.29,3066.71 6485.63,2954.37 6720.21,2954.37 6774.86,2899.73 6774.86,2891.71 6774.86,2468.04 6765.19,2458.37 6732.86,2458.37 6665.19,2390.71 6665.19,2288.55 v2(6695.04,2258.7) ; v2@6684.04,2258.7 ccw(c6657.48,2258.7) 6676.26,2277.48 ccw(c6695.04,2296.26) v2@6695.04,2269.7 ; v2@6688.04,2258.7 ccw(c6671.14,2258.7) 6683.09,2270.65 ccw(c6695.04,2282.6) v2@6695.04,2265.7
  Bottom Layer w4: R68.1@5748.18,3195 5796.57,3195 5800.57,3199 5800.57,3199.08 v1(5802.19,3200.71) ; R68.1@5751.94,3191.24 cw(c5761.02,3182.16) 5761.02,3195 cw(c5761.02,3207.84) R68.1@5751.94,3198.76 ; R68.1@5754.77,3188.41 cw(c5770.68,3172.5) 5770.68,3195 cw(c5770.68,3217.5) R68.1@5754.77,3201.59 ; 5765.47,3195 ccw(c5765.47,3237.42) v1@5795.47,3207.43 ; 5775.13,3195 ccw(c5775.13,3227.77) v1@5798.3,3204.6 ; 5784.79,3195 ccw(c5784.79,3218.11) v1@5801.13,3201.77
DB_JTAG.SOFT.TCK: U8.AF14 U30.W9 | length 3888.8
  Top Layer w4: v1@5291.81,2781.76 ccw(c5275.59,2797.98) 5298.52,2797.98 ccw(c5321.46,2797.98) v1@5305.24,2781.76 ; v1@5294.64,2778.93 ccw(c5285.25,2788.32) 5298.52,2788.32 ccw(c5311.8,2788.32) v1@5302.41,2778.93 ; v1(5298.52,2775.04) 5298.52,2836.48 5285,2850 5285,2915 5311.15,2941.15 5338.89,2941.15 5357.81,2922.23 5372.57,2922.23 5383,2932.66 5383,2958.52 5423.52,2999.04 5423.52,3016.71 5415.19,3025.04 5415.19,3163.73 5390.19,3188.73 5390.19,3228.02 5398,3235.83 5398,3347.25 5392.5,3352.75 5392.5,3419.4 5364.7,3447.19 5364.7,3514.57 5390.19,3540.06 5390.19,3626.29 5409.69,3645.79 5409.69,3660 5409.69,3670 U8.AF14@5409.69,3697.87 ; U8.AF14@5404.38,3692.57 cw(c5391.58,3679.77) 5409.69,3679.77 cw(c5427.79,3679.77) U8.AF14@5414.99,3692.57 ; U8.AF14@5404.49,3692.68 cw(c5391.96,3680.15) 5409.69,3680.15 cw(c5427.41,3680.15) U8.AF14@5414.88,3692.68
  Top Layer w8: v2@6655.67,1934.74 cw(c6655.67,1913.01) 6671.03,1928.38 cw(c6686.4,1943.74) v2@6664.67,1943.74 ; v2(6655.67,1943.74) U30.W9@6675.35,1924.06 ; U30.W9@6669.51,1924.06 ccw(c6655.41,1924.06) 6665.38,1934.03 ccw(c6675.35,1944) U30.W9@6675.35,1929.9
  MidLayer1 w4: v1@5264.02,1925.04 ccw(c5241.09,1925.04) 5257.31,1941.26 ccw(c5273.52,1957.48) v1@5273.52,1934.54 ; v1@5268.02,1925.04 ccw(c5254.75,1925.04) 5264.14,1934.43 ccw(c5273.52,1943.82) v1@5273.52,1930.54 ; v1(5273.52,1925.04) 5208.4,1990.16 5208.4,2448.61 5273.81,2514.01 5273.81,2705.29 5298.52,2730 v1(5298.52,2775.04) ; v1@5291.81,2768.32 cw(c5275.59,2752.11) 5298.52,2752.11 cw(c5321.46,2752.11) v1@5305.24,2768.32 ; v1@5294.64,2771.15 cw(c5285.25,2761.76) 5298.52,2761.76 cw(c5311.8,2761.76) v1@5302.41,2771.15
  MidLayer2 w4: v1@5273.52,1915.54 cw(c5273.52,1892.61) 5289.74,1908.82 cw(c5305.96,1925.04) v1@5283.02,1925.04 ; v1@5273.52,1919.54 cw(c5273.52,1906.26) 5282.91,1915.65 cw(c5292.3,1925.04) v1@5279.02,1925.04 ; v1(5273.52,1925.04) 5316.7,1881.87 5747.27,1881.87 5766.28,1900.87 5792.68,1900.87 5841.51,1949.71 6302.54,1949.71 6328.54,1923.71 6637.52,1923.71 6655.52,1941.71 6655.67,1941.71 v2(6655.67,1943.74) ; 6638.47,1924.65 ccw(c6623.01,1940.11) v2@6644.74,1942.52 ; 6640.11,1926.3 cw(c6655.67,1910.74) v2@6655.67,1932.74 ; 6644.35,1930.54 ccw(c6633.6,1941.29) v2@6648.71,1942.97 ; 6646.94,1933.12 cw(c6655.67,1924.4) v2@6655.67,1936.74
DB_JTAG.SOFT.TDI: U8.AA19 U30.T4 | length 3088
  Top Layer w4: U8.AA19@5606.54,3887.22 cw(c5606.54,3869.12) 5619.34,3881.92 cw(c5632.14,3894.72) U8.AA19@5614.04,3894.72 ; U8.AA19@5606.54,3887.38 cw(c5606.54,3869.66) 5619.07,3882.19 cw(c5631.6,3894.72) U8.AA19@5613.88,3894.72 ; U8.AA19@5606.54,3894.72 v3(5626.22,3875.04) ; 5613.42,3887.84 cw(c5600.61,3875.04) 5618.72,3875.04 ccw(c5600.61,3875.04) 5613.42,3887.84 ; 5613.42,3887.84 ccw(c5626.22,3900.65) 5626.22,3882.54 cw(c5626.22,3900.65) 5613.42,3887.84
  Top Layer w8: v2@6773.78,2131.59 cw(c6773.78,2109.86) 6789.14,2125.23 cw(c6804.51,2140.59) v2@6782.78,2140.59 ; v2(6773.78,2140.59) U30.T4@6793.46,2120.91 ; U30.T4@6787.62,2120.91 ccw(c6773.52,2120.91) 6783.49,2130.88 ccw(c6793.46,2140.85) U30.T4@6793.46,2126.75
  MidLayer1 w4: v3@5625.57,3867.57 cw(c5623.99,3849.53) 5637.86,3861.17 ; v3@5633.69,3874.39 ccw(c5651.73,3872.81) 5637.86,3861.17 ; 5650.08,3798.23 5650.08,3812.16 ; v1@5908.47,2418.32 ccw(c5892.26,2402.11) 5892.26,2425.04 ccw(c5892.26,2447.98) v1@5908.47,2431.76 ; v1@5911.3,2421.15 ccw(c5901.91,2411.76) 5901.91,2425.04 ccw(c5901.91,2438.32) v1@5911.3,2428.93 ; v1(5915.19,2425.04) 5819.96,2425.04 5806.86,2438.14 5806.86,2653.71 5748.36,2712.21 5748.36,2896.13 5739.88,2904.6 5700.19,2944.29 5700.19,3316.33 5672.19,3344.33 5672.19,3393.35 5698.52,3419.69 5698.52,3485.75 5690.19,3494.08 5690.19,3500.04 5650.08,3540.15 5650.08,3660 5650.08,3670 5650.08,3718.62 5650.08,3738.04 5650.08,3812.16 ; 5637.86,3861.17 cw(c5608.35,3831.66) 5650.08,3831.66 5650.08,3812.16
  MidLayer2 w4: v1@5915.19,2415.54 cw(c5915.19,2392.61) 5931.41,2408.82 cw(c5947.63,2425.04) v1@5924.69,2425.04 ; v1@5915.19,2419.54 cw(c5915.19,2406.26) 5924.58,2415.65 cw(c5933.97,2425.04) v1@5920.69,2425.04 ; v1(5915.19,2425.04) 5940.19,2400.04 5940.19,2341.71 6023.52,2258.37 6306.86,2258.37 6365.19,2200.04 6370.86,2194.37 6424.45,2194.37 6459.27,2159.55 6498.45,2120.37 6748.52,2120.37 6765.19,2137.04 6765.19,2141.71 v2@6773.78,2141.71 ; 6753.23,2125.08 cw(c6773.78,2104.52) v2@6773.78,2133.59 ; 6758.57,2130.42 ccw(c6748.39,2140.59) v2@6762.78,2140.59 ; 6760.05,2131.91 cw(c6773.78,2118.18) v2@6773.78,2137.59
DB_JTAG.SOFT.TDO: U8.AC20 U30.T3 | length 3636.6
  Top Layer w4: U8.AC20@5645.91,3808.48 cw(c5645.91,3790.38) 5658.71,3803.18 cw(c5671.51,3815.98) U8.AC20@5653.41,3815.98 ; U8.AC20@5645.91,3808.64 cw(c5645.91,3790.92) 5658.44,3803.45 cw(c5670.97,3815.98) U8.AC20@5653.25,3815.98 ; U8.AC20@5645.91,3815.98 v3(5665.59,3796.3) ; v1(5831.86,2616.71) 5880.19,2665.04 v1(5880.19,2783.37) ; v1@5831.86,2622.21 ccw(c5831.86,2635.49) 5841.25,2626.1 ccw(c5850.64,2616.71) v1@5837.36,2616.71 ; v1@5831.86,2626.21 ccw(c5831.86,2649.14) 5848.07,2632.93 ccw(c5864.29,2616.71) v1@5841.36,2616.71 ; v1@5873.47,2776.66 cw(c5857.26,2760.44) 5880.19,2760.44 cw(c5903.13,2760.44) v1@5886.91,2776.66 ; v1@5876.3,2779.49 cw(c5866.91,2770.1) 5880.19,2770.1 cw(c5893.47,2770.1) v1@5884.08,2779.49 ; v1(6573.52,2283.37) 6623.37,2283.37 6640.04,2300.04 v1(6692.86,2300.04) ; v1@6577.41,2279.49 cw(c6586.8,2270.1) 6586.8,2283.37 cw(c6586.8,2296.65) v1@6577.41,2287.26 ; v1@6580.24,2276.66 cw(c6596.46,2260.44) 6596.46,2283.37 cw(c6596.46,2306.31) v1@6580.24,2290.09 ; v1@6686.14,2293.32 ccw(c6669.92,2277.11) 6669.92,2300.04 ccw(c6669.92,2322.98) v1@6686.14,2306.76 ; v1@6688.97,2296.15 ccw(c6679.58,2286.76) 6679.58,2300.04 ccw(c6679.58,2313.32) v1@6688.97,2303.93 ; 5652.79,3809.1 cw(c5639.98,3796.3) 5658.09,3796.3 ccw(c5639.98,3796.3) 5652.79,3809.1 ; 5652.79,3809.1 ccw(c5665.59,3821.91) 5665.59,3803.8 cw(c5665.59,3821.91) 5652.79,3809.1
  Top Layer w8: v2@6773.78,2170.96 cw(c6773.78,2149.23) 6789.14,2164.6 cw(c6804.51,2179.96) v2@6782.78,2179.96 ; v2(6773.78,2179.96) U30.T3@6793.46,2160.28 ; U30.T3@6787.62,2160.28 ccw(c6773.52,2160.28) 6783.49,2170.25 ccw(c6793.46,2180.22) U30.T3@6793.46,2166.12
  MidLayer1 w4: v3@5660.4,3791.11 cw(c5647.86,3778.57) 5665.59,3778.57 cw(c5683.32,3778.57) v3@5670.78,3791.11 ; v3(5665.59,3796.3) 5665.59,3718.62 5665.59,3670 5665.59,3660 5665.59,3610.73 5658.08,3603.23 5658.08,3543.46 5698.52,3503.02 5698.52,3497.06 5706.86,3488.73 5706.86,3416.71 5681.86,3391.71 5681.86,3375.71 5688.05,3369.52 5697.38,3369.52 5709.61,3357.29 5709.61,3334.61 5708.19,3333.19 5708.19,2947.61 5756.86,2898.94 5756.86,2715.02 5815.19,2656.69 5815.19,2633.37 v1(5831.86,2616.71) ; v1@5822.36,2616.71 ccw(c5799.42,2616.71) 5815.64,2632.93 ccw(c5831.86,2649.14) v1@5831.86,2626.21 ; v1@5826.36,2616.71 ccw(c5813.08,2616.71) 5822.47,2626.1 ccw(c5831.86,2635.49) v1@5831.86,2622.21 ; 5665.59,3778.19 cw(c5683.7,3778.19) 5670.89,3791 ccw(c5683.7,3778.19) 5665.59,3778.19 ; 5665.59,3778.19 ccw(c5647.48,3778.19) 5660.29,3791 cw(c5647.48,3778.19) 5665.59,3778.19
  MidLayer2 w4: v1(5880.19,2783.37) 5880.19,2769.75 6008.23,2641.71 6306.86,2641.71 6440.19,2508.37 6440.19,2450.04 6523.52,2366.71 6523.52,2341.71 6540.19,2325.04 6565.19,2325.04 6585.15,2345 6613.52,2345 6623.52,2335 6623.52,2317.04 6589.86,2283.37 ; v1(6573.52,2283.37) 6589.86,2283.37 ; v1@6581.78,2278.68 cw(c6589.86,2274.09) 6589.86,2283.37 ; v1@6581.78,2288.07 ccw(c6589.86,2292.66) 6589.86,2283.37
  Bottom Layer w4: v1@6690.42,2300.58 ccw(c6704.05,2297.59) 6694.18,2287.72 ; v1(6692.86,2300.04) 6692.86,2289.04 6715.19,2266.71 6715.19,2247.37 6723.52,2239.04 6741.86,2239.04 6753.52,2227.37 6753.52,2212.37 6779.86,2186.04 6781.86,2184.04 6781.86,2179.96 v2(6773.78,2179.96) ; v1@6694.32,2299.72 ccw(c6712.53,2295.73) 6699.35,2282.55 ; v1@6698.23,2298.86 ccw(c6721.01,2293.87) 6704.52,2277.38 ; v1@6702.14,2298.01 ccw(c6729.49,2292.01) 6709.69,2272.21 ; 6754.06,2211.84 cw(c6723.33,2181.1) v2@6766.78,2180.12 ; 6760.68,2205.22 cw(c6736.27,2180.81) v2@6770.78,2180.03 ; 6767.29,2198.6 cw(c6749.21,2180.52) v2@6774.78,2179.94
DB_JTAG.SOFT.TMS: U8.AB20 U30.T2 | length 3225.4
  Top Layer w4: U8.AB20@5645.91,3847.85 cw(c5645.91,3829.75) 5658.71,3842.55 cw(c5671.51,3855.35) U8.AB20@5653.41,3855.35 ; U8.AB20@5645.91,3848.01 cw(c5645.91,3830.29) 5658.44,3842.82 cw(c5670.97,3855.35) U8.AB20@5653.25,3855.35 ; U8.AB20@5645.91,3855.35 v3(5665.59,3835.67) ; 5652.79,3848.47 cw(c5639.98,3835.67) 5658.09,3835.67 ccw(c5639.98,3835.67) 5652.79,3848.47 ; 5652.79,3848.47 ccw(c5665.59,3861.28) 5665.59,3843.17 cw(c5665.59,3861.28) 5652.79,3848.47
  Top Layer w8: v2@6773.78,2210.33 cw(c6773.78,2188.6) 6789.14,2203.97 cw(c6804.51,2219.33) v2@6782.78,2219.33 ; v2(6773.78,2219.33) U30.T2@6793.46,2199.65 ; U30.T2@6787.62,2199.65 ccw(c6773.52,2199.65) 6783.49,2209.62 ccw(c6793.46,2219.59) U30.T2@6793.46,2205.49
  MidLayer1 w4: v3@5664.94,3828.2 cw(c5663.36,3810.16) 5677.23,3821.8 cw(c5691.1,3833.44) v3@5673.06,3835.02 ; 5676.99,3822.09 cw(c5667.05,3812.16) 5681.1,3812.16 5681.1,3718.62 5681.1,3670 5681.1,3660 5681.1,3633.47 5688.64,3625.93 5731.86,3582.71 5731.86,3550.71 5773.52,3509.04 5865.54,3509.04 5895,3479.58 5915.19,3459.4 5915.19,3350.04 5957.86,3307.37 5962,3303.23 5962,3282.5 5948.52,3269.02 5948.52,3258.37 5914.19,3224.04 5914.19,3034.37 5934.19,3014.37 5934.19,2935.71 5906.86,2908.37 5906.86,2837.36 5898.52,2829.02 5898.52,2801.1 5905.69,2793.94 5905.69,2772.81 5898.52,2765.65 5898.52,2642.32 5973.52,2567.32 5973.52,2491.71 6131.86,2333.37 v1(6165.19,2333.37) ; v1@6158.47,2326.66 ccw(c6142.26,2310.44) 6142.26,2333.37 ccw(c6142.26,2356.31) v1@6158.47,2340.09 ; v1@6161.3,2329.49 ccw(c6151.91,2320.1) 6151.91,2333.37 ccw(c6151.91,2346.65) v1@6161.3,2337.26
  Bottom Layer w4: v1@6158.47,2326.66 cw(c6142.26,2310.44) 6165.19,2310.44 cw(c6188.13,2310.44) v1@6171.91,2326.66 ; v1@6161.3,2329.49 cw(c6151.91,2320.1) 6165.19,2320.1 cw(c6178.47,2320.1) v1@6169.08,2329.49 ; v1(6165.19,2333.37) 6165.19,2266.71 6306.86,2125.04 6331.86,2125.04 6390.19,2183.37 6390.19,2216.71 6549.52,2376.04 6648.48,2376.04 6746.94,2277.59 6754.52,2270 6754.52,2250 6754.52,2241.71 v2@6776.9,2219.33 ; 6752.96,2243.27 cw(c6729.27,2219.57) v2@6762.78,2219.39 ; 6759.74,2236.49 cw(c6742.75,2219.5) v2@6766.78,2219.37 ; 6760.33,2235.9 ccw(c6773.78,2249.35) v2@6773.78,2230.33 ; v2(6773.78,2219.33) v2@6776.9,2219.33 ; v2@6776.9,2219.33 6781.86,2219.33 6781.86,2216.71 6779.52,2216.71 v2@6776.9,2219.33
DB_MEM.BUS_A1: U7.E2 U8.AD15 U61.82 | length 6240.3
  Top Layer w4: v1@5435,3444.62 v1(5435,3440) 5460,3465 5460,3495 ; v1@5435,3445.5 ccw(c5435,3458.78) 5444.39,3449.39 ccw(c5453.78,3440) v1@5440.5,3440 ; v1@5435,3449.5 ccw(c5435,3472.43) 5451.22,3456.22 ccw(c5467.43,3440) v1@5444.5,3440 ; U8.AD15@5449.06,3769.27 cw(c5449.06,3751.55) 5461.59,3764.08 ; U8.AD15@5456.4,3776.61 ccw(c5474.12,3776.61) 5461.59,3764.08 ; 5460,3466.77 5460,3495 ; U61.82@5960.87,2821.32 cw(c5950.45,2810.89) 5965.19,2810.89 ; U61.82@5962.33,2854.29 ccw(c5960.84,2858.37) 5965.19,2858.37 ; U61.82@5963.7,2850.53 cw(c5979.04,2850.53) 5968.19,2861.38 ; 5965.19,2818.09 cw(c5969.76,2818.09) U61.82@5966.53,2821.32 ; U61.82@5965.19,2837.34 5965.19,2775.04 5981.86,2758.37 5998.52,2758.37 6073.52,2683.37 6120.54,2683.37 6170.54,2733.37 6206.86,2733.37 6240.19,2766.71 6240.19,2780.37 6261.52,2801.71 ; U61.82@5965.19,2838.83 5965.19,2858.37 ; 5965.19,2856.59 ccw(c5969.76,2856.59) U61.82@5966.53,2853.36 ; U61.82@5967.7,2850.53 cw(c5992.7,2850.53) v1@5975.02,2868.21 ; v1@5972.36,2875.04 cw(c5949.42,2875.04) 5965.64,2858.82 cw(c5981.86,2842.61) v1@5981.86,2865.54 ; v1@5976.36,2875.04 cw(c5963.08,2875.04) 5972.47,2865.65 cw(c5981.86,2856.26) v1@5981.86,2869.54 ; v1(5981.86,2875.04) 5965.19,2858.37 ; v1@6272.51,2796.12 ccw(c6261.52,2788.12) 6261.52,2801.71 ; v1@6272.51,2807.3 cw(c6261.52,2815.29) 6261.52,2801.71 ; v1(6280.19,2801.71) 6261.52,2801.71 ; 5460,3495 5460,3503.45 5473.52,3516.97 5473.52,3651.25 5472.91,3651.25 5472.92,3655.26 5472.92,3660 5472.92,3670 5472.92,3736.73 ccw(c5434.24,3736.73) 5461.59,3764.08
  Top Layer w8: v2@7810.63,4594.11 cw(c7810.63,4572.38) 7825.99,4587.75 cw(c7841.36,4603.11) v2@7819.63,4603.11 ; v2(7810.63,4603.11) U7.E2@7830.32,4583.43 ; U7.E2@7824.32,4583.43 ccw(c7809.83,4583.43) 7820.07,4593.67 ccw(c7830.32,4603.91) U7.E2@7830.32,4589.43
  MidLayer1 w4: v1(7752.19,3241.71) 7740.19,3253.71 7740.19,3600.67 7799.19,3659.67 7799.19,4187.34 7840.19,4228.34 7840.19,4573.55 v2(7810.63,4603.11) ; v2@7810.63,4592.11 cw(c7810.63,4565.56) 7829.41,4584.33 cw(c7848.19,4603.11) v2@7821.63,4603.11 ; v2@7810.63,4596.11 cw(c7810.63,4579.21) 7822.58,4591.16 cw(c7834.53,4603.11) v2@7817.63,4603.11
  MidLayer2 w4: v1@5428.28,3433.28 cw(c5412.06,3417.06) 5435,3417.06 cw(c5457.93,3417.06) v1@5441.72,3433.28 ; v1@5431.11,3436.11 cw(c5421.72,3426.72) 5435,3426.72 cw(c5448.28,3426.72) v1@5438.89,3436.11 ; v1@5440.19,3439.86 5440.05,3440 v1(5435,3440) 5435,3382.21 5445,3372.21 5445,3336.02 5432.43,3323.44 5432.43,3308.94 5443,3298.37 5456.86,3298.37 5466.19,3289.04 5469.19,3286.04 5469.19,3251.67 5439.86,3222.34 5439.86,3190 5439.86,3090 5439.86,3065.04 5471.53,3033.37 5548.52,3033.37 5840.19,3033.37 5981.86,2891.71 ; v1@5977.02,2883.22 ccw(c5971.99,2891.71) 5981.86,2891.71 ; v1(5981.86,2875.04) 5981.86,2891.71 ; v1@5986.7,2883.22 cw(c5991.73,2891.71) 5981.86,2891.71
  Bottom Layer w4: v1(6280.19,2801.71) 6292.52,2789.37 6423.52,2789.37 6425.86,2791.71 6668.29,2791.71 6676.58,2800 6725,2800 6834.84,2800.04 ; 6834.8,2800 6834.84,2800.04 ; v1(7752.19,3241.71) 7823.52,3241.71 7840.19,3225.04 7840.19,3091.71 7823.52,3075.04 7800,3075.04 7740.91,3134.13 7635.87,3134.13 7610.54,3159.46 7514.11,3159.46 7315.19,3358.37 7215.19,3358.37 7198.52,3341.71 7198.52,3308.37 7245,3261.9 7245,3096.52 7156.86,3008.37 7023.52,2875.04 6909.84,2875.04 6834.84,2800.04 ; v1@7756.08,3237.82 cw(c7765.47,3228.43) 7765.47,3241.71 cw(c7765.47,3254.99) v1@7756.08,3245.6 ; v1@7758.91,3234.99 cw(c7775.13,3218.77) 7775.13,3241.71 cw(c7775.13,3264.64) v1@7758.91,3248.43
